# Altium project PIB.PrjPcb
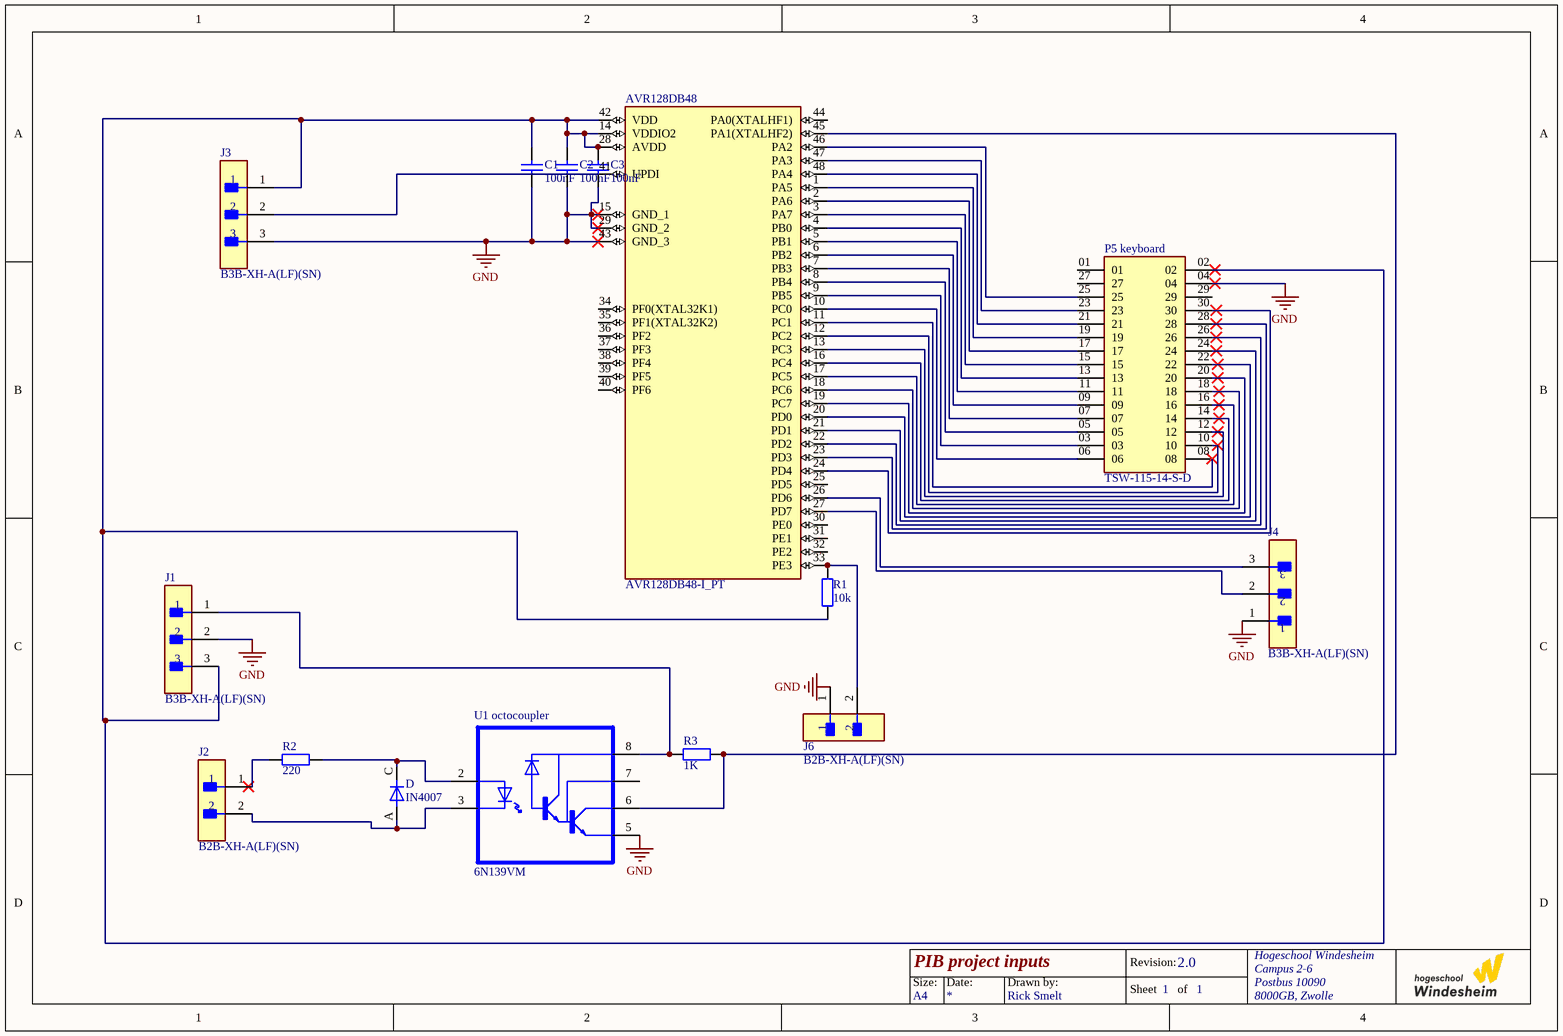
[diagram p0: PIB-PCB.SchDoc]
1 sheet, 15 parts. Net scope: global (net labels, ports and power ports of the same name join across sheets).
Board file: PCB-PCB.PcbDoc

## Sheet PIB-PCB.SchDoc: PIB project inputs
size A4; DrawnBy: Rick Smelt; Revision: 2.0; SheetNumber: 1; SheetTotal: 1; SPICEModelCacheWKKWDLWO: <root> / <DocumentId>WKKWDLWO</DocumentId> / </root>

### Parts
AVR128DB48  AVR128DB48-I_PT  [QFP50P900X900X120-48N]
C1  100nF  [C1206]
C2  100nF  [C1206]
C3  100nF  [C1206]
D  IN4007  [DIOAD1070W78L470D235P]
J1  B3B-XH-A(LF)(SN)  [FP-B3B-XH-A_LF_SN-MFG]
J2  B2B-XH-A(LF)(SN)  [FP-B2B-XH-A_LF_SN-MFG]
J3  B3B-XH-A(LF)(SN)  [FP-B3B-XH-A_LF_SN-MFG]
J4  B3B-XH-A(LF)(SN)  [FP-B3B-XH-A_LF_SN-MFG]
J6  B2B-XH-A(LF)(SN)  [FP-B2B-XH-A_LF_SN-MFG]
P5_keyboard  TSW-115-14-S-D  [SAMTEC_TSW-115-14-S-D]
R1  10k  [R1206]
R2  220  [R1206]
R3  1K  [R1206]
U1_octocoupler  6N139VM  [DIP762W50P254L977H451Q8]

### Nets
GND: AVR128DB48.15(GND_1) AVR128DB48.29(GND_2) AVR128DB48.43(GND_3) C1.1 C2.1 C3.1 J1.2 J3.3 J4.1 J6.1 P5_keyboard.04 U1_octocoupler.5(GND)
NetAVR128DB48_1: AVR128DB48.1(PA5) P5_keyboard.19
NetAVR128DB48_2: AVR128DB48.2(PA6) P5_keyboard.17
NetAVR128DB48_3: AVR128DB48.3(PA7) P5_keyboard.15
NetAVR128DB48_4: AVR128DB48.4(PB0) P5_keyboard.13
NetAVR128DB48_5: AVR128DB48.5(PB1) P5_keyboard.11
NetAVR128DB48_6: AVR128DB48.6(PB2) P5_keyboard.09
NetAVR128DB48_7: AVR128DB48.7(PB3) P5_keyboard.07
NetAVR128DB48_8: AVR128DB48.8(PB4) P5_keyboard.05
NetAVR128DB48_9: AVR128DB48.9(PB5) P5_keyboard.03
NetAVR128DB48_10: AVR128DB48.10(PC0) P5_keyboard.06
NetAVR128DB48_11: AVR128DB48.11(PC1) P5_keyboard.08
NetAVR128DB48_12: AVR128DB48.12(PC2) P5_keyboard.10
NetAVR128DB48_13: AVR128DB48.13(PC3) P5_keyboard.12
NetAVR128DB48_14: AVR128DB48.14(VDDIO2) AVR128DB48.28(AVDD) AVR128DB48.42(VDD) C1.2 C2.2 C3.2 J1.3 J3.1 P5_keyboard.02 R1.1
NetAVR128DB48_16: AVR128DB48.16(PC4) P5_keyboard.14
NetAVR128DB48_17: AVR128DB48.17(PC5) P5_keyboard.16
NetAVR128DB48_18: AVR128DB48.18(PC6) P5_keyboard.18
NetAVR128DB48_19: AVR128DB48.19(PC7) P5_keyboard.20
NetAVR128DB48_20: AVR128DB48.20(PD0) P5_keyboard.22
NetAVR128DB48_21: AVR128DB48.21(PD1) P5_keyboard.24
NetAVR128DB48_22: AVR128DB48.22(PD2) P5_keyboard.26
NetAVR128DB48_23: AVR128DB48.23(PD3) P5_keyboard.28
NetAVR128DB48_24: AVR128DB48.24(PD4) P5_keyboard.30
NetAVR128DB48_26: AVR128DB48.26(PD6) J4.3
NetAVR128DB48_27: AVR128DB48.27(PD7) J4.2
NetAVR128DB48_33: AVR128DB48.33(PE3) J6.2 R1.2
NetAVR128DB48_41: AVR128DB48.41(UPDI) J3.2
NetAVR128DB48_45: AVR128DB48.45(PA1(XTALHF2)) R3.2 U1_octocoupler.6(VO)
NetAVR128DB48_46: AVR128DB48.46(PA2) P5_keyboard.25
NetAVR128DB48_47: AVR128DB48.47(PA3) P5_keyboard.23
NetAVR128DB48_48: AVR128DB48.48(PA4) P5_keyboard.21
NetD_A: D.A J2.2 U1_octocoupler.3(C)
NetD_C: D.C R2.2 U1_octocoupler.2(A)
NetJ1_1: J1.1 R3.1 U1_octocoupler.8(VCC)
NetJ2_1: J2.1 R2.1

Not connected (* = marked no-connect by the designer): AVR128DB48 25(PD5) 30(PE0) 31(PE1) 32(PE2) 34(PF0(XTAL32K1)) 35(PF1(XTAL32K2)) 36(PF2) 37(PF3) 38(PF4) 39(PF5) 40(PF6) 44(PA0(XTALHF1)); P5_keyboard 01 27 29; U1_octocoupler 7(VB)

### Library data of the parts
AVR128DB48 = AVR128DB48-I_PT: AVR AVRÂ® DB Microcontroller IC 8-Bit 24MHz 128KB (128K x 8) FLASH 48-TQFP (7x7); MF: Microchip Technology; MP: AVR128DB48-I/PT
C1-C3 = Capacitor_1206: SMD Capacitor 1206
D = IN4007: Diode Standard 1000V 1A Through Hole DO-204AL _DO-41_; MF: Vishay Semiconductor
J1 J3 J4 = CMP-17439-000014-3: CONN HEADER VERT 3POS 2.5MM; Max Voltage Rating (DC): 250V; Number of Positions: 3; Current Rating: 3A; Gender: Male; Wire/Cable Gauge: 22AWG; Contact Resistance: 20mR; Insulation Resistance: 1GR
J2 J6 = CMP-2000-05888-3: CONN HEADER VERT 2POS 2.5MM; Current Rating: 3A; Voltage Rating: 250V; Number of Contacts: 2; Contact Resistance: 20mR; Wire/Cable Gauge: 22AWG; Insulation Resistance: 1GR; Connector Type: Male Pin
R1-R3 = Resistor_1206: SMD Resistor 1206
U1_octocoupler = 6N139VM: High Speed Optocoupler, 100 kBd, Low Input Current, Photodiode Darlington Output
